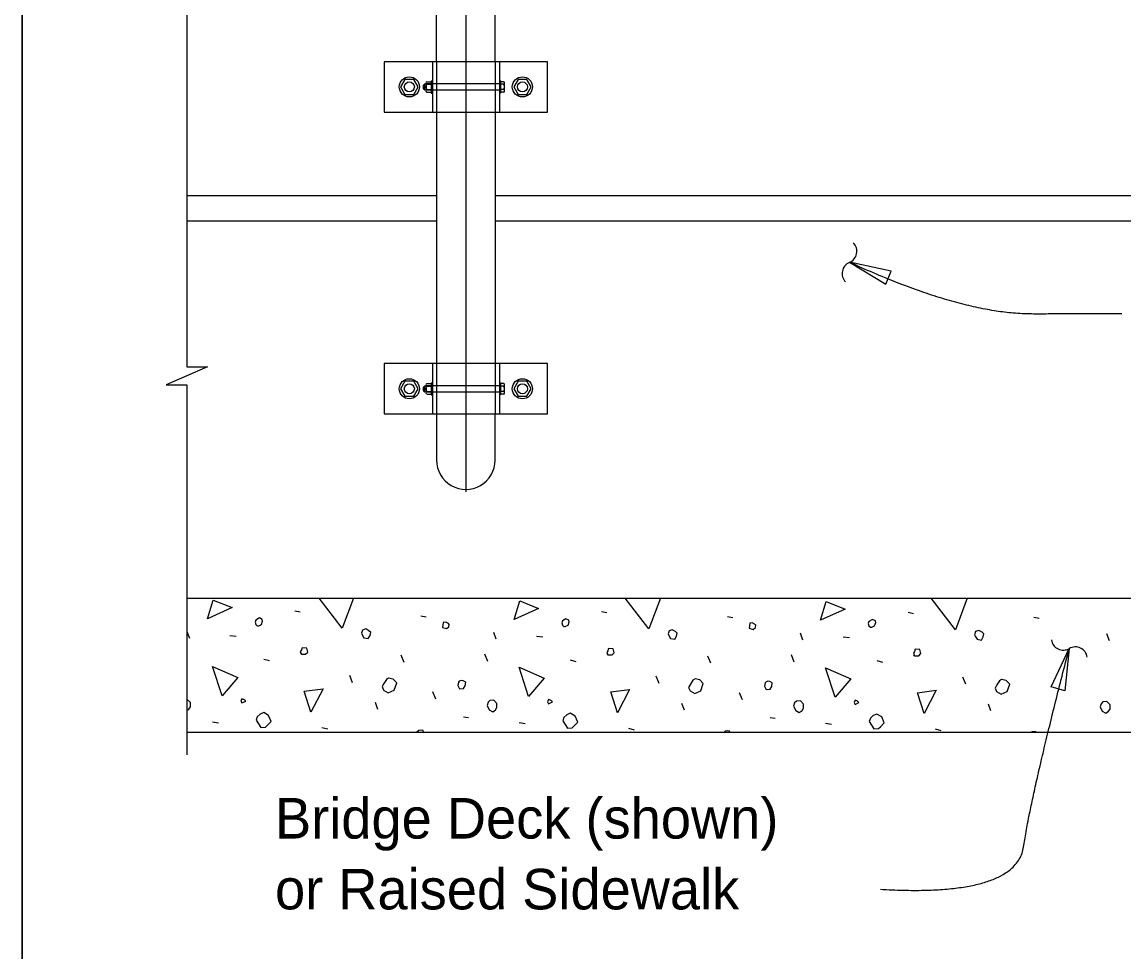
# Model space of a CAD drawing. Extents: x 0 to 41.2, y 0 to 26.
# Drawn here: x 0 to 5.48, y 12.38 to 17 of the extents above; entities that cross this region are included whole.
import ezdxf

# ---------------------------------------------------------------- set-up
doc = ezdxf.new("R2010")
doc.units = 0
for name, color, linetype in [('ActivePts-ConstElements', 7, 'Continuous'), ('CL_Major', 7, 'Continuous'), ('Dimension', 7, 'Continuous'), ('Miscellaneous', 7, 'Continuous'), ('Miscellaneous1', 7, 'Continuous'), ('SteelMisc', 7, 'Continuous'), ('SteelMisc_h', 7, 'Continuous'), ('SupstrConc', 7, 'Continuous')]:
    doc.layers.add(name, color=color, linetype=linetype)

msp = doc.modelspace()

# ---------------------------------------------------------------- linework, layer by layer
at = {"layer": 'ActivePts-ConstElements'}
msp.add_lwpolyline([(0, 0), (41.2106, 0), (41.2106, 25.96), (0, 25.96)], close=True, dxfattribs=at)
at = {"layer": 'CL_Major'}
msp.add_line((2.2062, 25.5043), (2.2062, 14.6639), dxfattribs=at)
at = {"layer": 'Dimension'}
for points in [[(0.8194, 20.1983), (0.8194, 19.1806), (0.9227, 19.1806), (0.8194, 19.1356), (0.716, 19.0906), (0.8194, 19.0906), (0.8194, 16.8862)], [(0.8194, 17.1362), (0.8194, 15.2854), (0.9227, 15.2854), (0.8194, 15.2404), (0.716, 15.1954), (0.8194, 15.1954), (0.8194, 13.3576)]]:
    msp.add_lwpolyline(points, dxfattribs=at)
for points in [[(4.1133, 15.8046), (4.2942, 15.6956), (4.32, 15.7612)], [(5.2051, 13.8856), (5.1828, 13.6755), (5.1149, 13.6946)]]:
    msp.add_lwpolyline(points, close=True, dxfattribs=at)
for centre, start, end in [((4.09, 15.8588), 292.7091, 44.4364), ((4.136, 15.7489), 112.7091, 224.4364), ((5.1759, 13.9368), 188.4294, 300.1567), ((5.2358, 13.8337), 8.4294, 120.1567)]:
    msp.add_arc(centre, 0.0596, start, end, dxfattribs=at)
for points in [[(5.467, 15.5476), (5.3703, 15.5476), (4.6709, 15.5476), (4.1132, 15.8046)], [(4.2666, 12.6889), (4.9423, 12.6495), (5.0161, 13.1567), (5.2052, 13.8855)]]:
    msp.add_open_spline(points, degree=2, dxfattribs=at)
at = {"layer": 'Miscellaneous'}
for p, q in [((1.9986, 16.6691), (1.9986, 16.6812)), ((2.0043, 16.6691), (2.0043, 16.6812)), ((1.9986, 15.1691), (1.9986, 15.1812)), ((2.0043, 15.1691), (2.0043, 15.1812)), ((1.3567, 14.0725), (1.3832, 14.0672)), ((1.9825, 14.0477), (2.009, 14.0424)), ((2.8805, 14.0689), (2.907, 14.0636)), ((3.5063, 14.0442), (3.5328, 14.0389)), ((4.4043, 14.0654), (4.4308, 14.0601)), ((5.0301, 14.0407), (5.0566, 14.0354)), ((0.8334, 13.9346), (0.821, 13.9682)), ((1.0332, 13.9505), (1.065, 13.947)), ((2.3572, 13.9311), (2.3448, 13.9646)), ((2.557, 13.947), (2.5888, 13.9434)), ((3.881, 13.9275), (3.8687, 13.9611)), ((4.0808, 13.9434), (4.1126, 13.9399)), ((5.4048, 13.924), (5.3925, 13.9576)), ((1.2011, 13.8321), (1.2294, 13.825)), ((1.8994, 13.8162), (1.8852, 13.8515)), ((2.3148, 13.8215), (2.3006, 13.8568)), ((2.7249, 13.8285), (2.7532, 13.8215)), ((3.4232, 13.8126), (3.409, 13.848)), ((3.8386, 13.8179), (3.8245, 13.8533)), ((4.2487, 13.825), (4.277, 13.8179)), ((1.643, 13.7154), (1.6289, 13.7507)), ((3.1669, 13.7119), (3.1527, 13.7472)), ((4.6907, 13.7083), (4.6765, 13.7437)), ((2.0567, 13.6341), (2.0426, 13.6694)), ((3.5805, 13.6305), (3.5664, 13.6659)), ((1.7686, 13.5828), (1.7562, 13.6164)), ((3.2924, 13.5793), (3.28, 13.6129)), ((4.8162, 13.5757), (4.8038, 13.6093)), ((2.1946, 13.5457), (2.2193, 13.5421)), ((3.7184, 13.5421), (3.7431, 13.5386)), ((0.9465, 13.5209), (0.9766, 13.5156)), ((1.491, 13.4927), (1.5193, 13.4856)), ((2.4704, 13.5174), (2.5004, 13.5121)), ((3.0148, 13.4891), (3.0431, 13.482)), ((3.9942, 13.5139), (4.0242, 13.5086)), ((4.5386, 13.4856), (4.5669, 13.4785))]:
    msp.add_line(p, q, dxfattribs=at)
for points in [[(1.5918, 13.9859), (1.4776, 14.1361)], [(1.6479, 14.1361), (1.5918, 13.9859)], [(3.1156, 13.9823), (2.9987, 14.1361)], [(3.1731, 14.1361), (3.1156, 13.9823)], [(4.6394, 13.9788), (4.5198, 14.1361)], [(4.6982, 14.1361), (4.6394, 13.9788)], [(0.9218, 14.0336), (0.9501, 14.1255), (1.0438, 14.0884), (0.9218, 14.0336)], [(2.4456, 14.0301), (2.4739, 14.122), (2.5676, 14.0849), (2.4456, 14.0301)], [(3.9694, 14.0265), (3.9977, 14.1184), (4.0914, 14.0813), (3.9694, 14.0265)], [(1.1693, 13.9982), (1.1763, 13.9982), (1.1905, 14.0053), (1.1958, 14.0212), (1.194, 14.0301), (1.1799, 14.0371), (1.1622, 14.0265), (1.1587, 14.0159), (1.1622, 14.0053), (1.1693, 13.9982)], [(2.6931, 13.9947), (2.7002, 13.9947), (2.7143, 14.0018), (2.7196, 14.0177), (2.7178, 14.0265), (2.7037, 14.0336), (2.686, 14.023), (2.6825, 14.0124), (2.686, 14.0018), (2.6931, 13.9947)], [(4.2169, 13.9912), (4.224, 13.9912), (4.2381, 13.9982), (4.2434, 14.0141), (4.2417, 14.023), (4.2275, 14.0301), (4.2098, 14.0194), (4.2063, 14.0088), (4.2098, 13.9982), (4.2169, 13.9912)], [(1.6908, 13.954), (1.6996, 13.9381), (1.7208, 13.9346), (1.7297, 13.9505), (1.7332, 13.9646), (1.7244, 13.9735), (1.7084, 13.9823), (1.6925, 13.977), (1.6872, 13.9611), (1.6908, 13.954)], [(2.0903, 13.9894), (2.1097, 13.9841), (2.1221, 13.9929), (2.1239, 14.0053), (2.1203, 14.0088), (2.1062, 14.0159), (2.0938, 14.0141), (2.0921, 14.0018), (2.0903, 13.9894)], [(3.2146, 13.9505), (3.2234, 13.9346), (3.2446, 13.9311), (3.2535, 13.947), (3.257, 13.9611), (3.2482, 13.9699), (3.2323, 13.9788), (3.2164, 13.9735), (3.211, 13.9576), (3.2146, 13.9505)], [(3.6141, 13.9859), (3.6335, 13.9806), (3.6459, 13.9894), (3.6477, 14.0018), (3.6442, 14.0053), (3.63, 14.0124), (3.6176, 14.0106), (3.6159, 13.9982), (3.6141, 13.9859)], [(4.7384, 13.947), (4.7472, 13.9311), (4.7685, 13.9275), (4.7773, 13.9434), (4.7808, 13.9576), (4.772, 13.9664), (4.7561, 13.9753), (4.7402, 13.9699), (4.7349, 13.954), (4.7384, 13.947)], [(1.3885, 13.8568), (1.4097, 13.8568), (1.4203, 13.8674), (1.415, 13.8869), (1.392, 13.8886), (1.3885, 13.878), (1.3832, 13.8692), (1.3885, 13.8568), (1.3849, 13.8603)], [(2.9123, 13.8533), (2.9335, 13.8533), (2.9441, 13.8639), (2.9388, 13.8833), (2.9158, 13.8851), (2.9123, 13.8745), (2.907, 13.8657), (2.9123, 13.8533), (2.9088, 13.8568)], [(4.4361, 13.8497), (4.4573, 13.8497), (4.4679, 13.8603), (4.4626, 13.8798), (4.4396, 13.8816), (4.4361, 13.871), (4.4308, 13.8621), (4.4361, 13.8497), (4.4326, 13.8533)], [(0.9943, 13.65), (0.9465, 13.7967), (1.0721, 13.7419), (0.9943, 13.65)], [(2.5181, 13.6464), (2.4704, 13.7932), (2.5959, 13.7384), (2.5181, 13.6464)], [(4.0419, 13.6429), (3.9942, 13.7896), (4.1197, 13.7348), (4.0419, 13.6429)], [(1.7968, 13.6783), (1.8198, 13.6659), (1.8499, 13.6783), (1.8622, 13.7154), (1.8446, 13.7331), (1.8216, 13.7384), (1.811, 13.7313), (1.7986, 13.7119), (1.7898, 13.6959), (1.7968, 13.6783)], [(2.1663, 13.7012), (2.1751, 13.6853), (2.1946, 13.6871), (2.2034, 13.6995), (2.2052, 13.7189), (2.1928, 13.7242), (2.184, 13.726), (2.1734, 13.7225), (2.1698, 13.7189), (2.1663, 13.7012)], [(3.3207, 13.6747), (3.3436, 13.6624), (3.3737, 13.6747), (3.3861, 13.7119), (3.3684, 13.7295), (3.3454, 13.7348), (3.3348, 13.7278), (3.3224, 13.7083), (3.3136, 13.6924), (3.3207, 13.6747)], [(3.6901, 13.6977), (3.699, 13.6818), (3.7184, 13.6836), (3.7272, 13.6959), (3.729, 13.7154), (3.7166, 13.7207), (3.7078, 13.7225), (3.6972, 13.7189), (3.6936, 13.7154), (3.6901, 13.6977)], [(4.8445, 13.6712), (4.8674, 13.6588), (4.8975, 13.6712), (4.9099, 13.7083), (4.8922, 13.726), (4.8692, 13.7313), (4.8586, 13.7242), (4.8462, 13.7048), (4.8374, 13.6889), (4.8445, 13.6712)], [(1.4362, 13.5687), (1.4026, 13.673), (1.4963, 13.6853), (1.4362, 13.5687)], [(2.96, 13.5651), (2.9264, 13.6694), (3.0201, 13.6818), (2.96, 13.5651)], [(4.4838, 13.5616), (4.4503, 13.6659), (4.5439, 13.6783), (4.4838, 13.5616)], [(0.8193, 13.5766), (0.8299, 13.5846), (0.8369, 13.5952), (0.8369, 13.6164), (0.821, 13.6323), (0.8193, 13.6321)], [(1.0933, 13.6146), (1.1127, 13.6235), (1.1056, 13.6305), (1.0933, 13.6358), (1.088, 13.6235), (1.0933, 13.6146)], [(2.3113, 13.6023), (2.3219, 13.581), (2.3395, 13.5704), (2.3537, 13.581), (2.3608, 13.5916), (2.3608, 13.6129), (2.3448, 13.6288), (2.3254, 13.627), (2.3166, 13.6182), (2.3113, 13.6023)], [(2.6171, 13.6111), (2.6365, 13.6199), (2.6295, 13.627), (2.6171, 13.6323), (2.6118, 13.6199), (2.6171, 13.6111)], [(3.8351, 13.5987), (3.8457, 13.5775), (3.8634, 13.5669), (3.8775, 13.5775), (3.8846, 13.5881), (3.8846, 13.6093), (3.8687, 13.6252), (3.8492, 13.6235), (3.8404, 13.6146), (3.8351, 13.5987)], [(4.1409, 13.6076), (4.1603, 13.6164), (4.1533, 13.6235), (4.1409, 13.6288), (4.1356, 13.6164), (4.1409, 13.6076)], [(5.3589, 13.5952), (5.3695, 13.574), (5.3872, 13.5634), (5.4013, 13.574), (5.4084, 13.5846), (5.4084, 13.6058), (5.3925, 13.6217), (5.373, 13.6199), (5.3642, 13.6111), (5.3589, 13.5952)], [(1.164, 13.5298), (1.187, 13.4927), (1.2099, 13.4944), (1.2188, 13.5033), (1.2382, 13.5227), (1.2258, 13.5528), (1.2011, 13.5669), (1.1834, 13.5598), (1.1693, 13.5457), (1.164, 13.5298)], [(2.6878, 13.5262), (2.7108, 13.4891), (2.7338, 13.4909), (2.7426, 13.4997), (2.762, 13.5192), (2.7497, 13.5492), (2.7249, 13.5634), (2.7072, 13.5563), (2.6931, 13.5421), (2.6878, 13.5262)], [(4.2116, 13.5227), (4.2346, 13.4856), (4.2576, 13.4873), (4.2664, 13.4962), (4.2859, 13.5156), (4.2735, 13.5457), (4.2487, 13.5598), (4.2311, 13.5528), (4.2169, 13.5386), (4.2116, 13.5227)], [(1.9949, 13.4695), (1.9931, 13.4785), (1.9842, 13.4803), (1.9718, 13.4785), (1.9628, 13.4695)], [(3.518, 13.4695), (3.5169, 13.475), (3.508, 13.4767), (3.4957, 13.475), (3.4901, 13.4695)], [(5.0411, 13.4695), (5.0407, 13.4714), (5.0318, 13.4732), (5.0195, 13.4714), (5.0175, 13.4695)]]:
    msp.add_lwpolyline(points, dxfattribs=at)
at = {"layer": 'Miscellaneous1'}
msp.add_lwpolyline([(0, 25.96), (41.2106, 25.96), (41.2106, 0), (0, 0)], close=True, dxfattribs=at)
at = {"layer": 'SteelMisc'}
for p, q in [((2.0603, 16.801), (2.0603, 17.4631)), ((2.352, 16.801), (2.352, 17.4631)), ((2.6121, 16.801), (1.8002, 16.801)), ((1.8002, 16.801), (1.8002, 16.551)), ((2.0395, 16.801), (2.0395, 16.551)), ((2.3728, 16.801), (2.3728, 16.551)), ((2.6121, 16.551), (2.6121, 16.801)), ((2.033, 16.7063), (2.033, 16.6457)), ((2.033, 16.7063), (2.0395, 16.7063)), ((2.3791, 16.7063), (2.3731, 16.7063)), ((2.3791, 16.7063), (2.3791, 16.6457)), ((1.9958, 16.684), (2.0014, 16.6906)), ((1.9958, 16.6663), (1.9958, 16.684)), ((1.9958, 16.6663), (2.0014, 16.6607)), ((2.0014, 16.6906), (2.008, 16.6906)), ((2.0014, 16.6607), (2.0014, 16.6906)), ((2.0014, 16.6607), (2.008, 16.6607)), ((2.008, 16.6939), (2.008, 16.6582)), ((2.0127, 16.689), (2.033, 16.689)), ((2.0127, 16.6631), (2.033, 16.6631)), ((2.0129, 16.702), (2.033, 16.702)), ((2.033, 16.702), (2.033, 16.65)), ((2.3938, 16.702), (2.3791, 16.702)), ((2.3939, 16.689), (2.3791, 16.689)), ((2.3939, 16.663), (2.3791, 16.663)), ((2.3989, 16.6566), (2.3989, 16.6955)), ((2.013, 16.65), (2.033, 16.65)), ((2.033, 16.6457), (2.0395, 16.6457)), ((2.3791, 16.6457), (2.3731, 16.6457)), ((2.3938, 16.65), (2.3791, 16.65)), ((1.8002, 16.551), (2.6121, 16.551)), ((2.0603, 16.551), (2.0603, 15.301)), ((2.352, 16.551), (2.352, 15.301)), ((2.6121, 15.301), (1.8002, 15.301)), ((1.8002, 15.301), (1.8002, 15.051)), ((2.0395, 15.301), (2.0395, 15.051)), ((2.3728, 15.301), (2.3728, 15.051)), ((2.6121, 15.051), (2.6121, 15.301)), ((1.9958, 15.184), (2.0014, 15.1906)), ((1.9958, 15.1663), (1.9958, 15.184)), ((2.0014, 15.1906), (2.008, 15.1906)), ((2.0014, 15.1607), (2.0014, 15.1906)), ((2.008, 15.1939), (2.008, 15.1582)), ((2.0127, 15.189), (2.033, 15.189)), ((2.0129, 15.202), (2.033, 15.202)), ((2.033, 15.2063), (2.033, 15.1457)), ((2.033, 15.2063), (2.0395, 15.2063)), ((2.033, 15.202), (2.033, 15.15)), ((2.3791, 15.2063), (2.3731, 15.2063)), ((2.3791, 15.2063), (2.3791, 15.1457)), ((2.3938, 15.202), (2.3791, 15.202)), ((2.3939, 15.189), (2.3791, 15.189)), ((2.3989, 15.1566), (2.3989, 15.1955)), ((1.9958, 15.1663), (2.0014, 15.1607)), ((2.0014, 15.1607), (2.008, 15.1607)), ((2.0127, 15.1631), (2.033, 15.1631)), ((2.013, 15.15), (2.033, 15.15)), ((2.033, 15.1457), (2.0395, 15.1457)), ((2.3791, 15.1457), (2.3731, 15.1457)), ((2.3939, 15.163), (2.3791, 15.163)), ((2.3938, 15.15), (2.3791, 15.15)), ((1.8002, 15.051), (2.6121, 15.051)), ((2.0602, 15.051), (2.0602, 14.8218)), ((2.3519, 14.8218), (2.3519, 15.051))]:
    msp.add_line(p, q, dxfattribs=at)
for points in [[(1.9468, 16.7135), (1.9035, 16.7135), (1.8818, 16.676), (1.9035, 16.6385), (1.9468, 16.6385), (1.9685, 16.676)], [(2.5088, 16.7135), (2.4655, 16.7135), (2.4438, 16.676), (2.4655, 16.6385), (2.5088, 16.6385), (2.5305, 16.676)], [(1.9468, 15.2135), (1.9035, 15.2135), (1.8818, 15.176), (1.9035, 15.1385), (1.9468, 15.1385), (1.9685, 15.176)], [(2.5088, 15.2135), (2.4655, 15.2135), (2.4438, 15.176), (2.4655, 15.1385), (2.5088, 15.1385), (2.5305, 15.176)]]:
    msp.add_lwpolyline(points, close=True, dxfattribs=at)
for centre, radius in [((1.9252, 16.676), 0.05), ((2.4871, 16.676), 0.05), ((1.9252, 16.676), 0.025), ((2.4871, 16.676), 0.025), ((1.9252, 15.176), 0.05), ((1.9252, 15.176), 0.025), ((2.4871, 15.176), 0.05), ((2.4871, 15.176), 0.025)]:
    msp.add_circle(centre, radius, dxfattribs=at)
for centre, radius, start, end in [((2.0145, 16.6955), 0.00674, 104.4891, 254.1889), ((2.0274, 16.676), 0.0196, 138.628, 221.372), ((2.0145, 16.6565), 0.00673, 105.7823, 255.5404), ((2.3921, 16.6955), 0.00673, 285.7823, 75.5404), ((2.3921, 16.6565), 0.00674, 284.4891, 74.1889), ((2.3792, 16.676), 0.0196, 318.628, 41.372), ((2.0145, 15.1955), 0.00674, 104.4891, 254.1889), ((2.0274, 15.176), 0.0196, 138.628, 221.372), ((2.3921, 15.1955), 0.00673, 285.7823, 75.5404), ((2.3792, 15.176), 0.0196, 318.628, 41.372), ((2.0145, 15.1565), 0.00673, 105.7823, 255.5404), ((2.3921, 15.1565), 0.00674, 284.4891, 74.1889)]:
    msp.add_arc(centre, radius, start, end, dxfattribs=at)
msp.add_ellipse((2.2062, 14.8218), major_axis=(0, 0.1458), ratio=0.999499, start_param=1.570796, end_param=4.712389, dxfattribs=at)
at = {"layer": 'SteelMisc_h'}
for p, q in [((2.0603, 16.801), (2.0603, 16.551)), ((2.352, 16.801), (2.352, 16.551)), ((2.3729, 16.6906), (2.008, 16.6906)), ((2.008, 16.6607), (2.3729, 16.6607)), ((2.0603, 15.301), (2.0603, 15.051)), ((2.352, 15.301), (2.352, 15.051)), ((2.3729, 15.1906), (2.008, 15.1906)), ((2.008, 15.1607), (2.3729, 15.1607))]:
    msp.add_line(p, q, dxfattribs=at)
at = {"layer": 'SupstrConc'}
for p, q in [((0.8193, 16.1361), (2.0603, 16.1361)), ((2.352, 16.1361), (12.0604, 16.1361)), ((0.8193, 16.0111), (2.0603, 16.0111)), ((2.352, 16.0111), (12.0604, 16.0111)), ((0.8193, 14.1361), (23.5931, 14.1361)), ((0.8193, 13.4695), (23.5931, 13.4695))]:
    msp.add_line(p, q, dxfattribs=at)

# ---------------------------------------------------------------- texts
at = {"layer": 'Dimension'}
for s, p in [('Bridge Deck (shown)', (1.2575, 12.9409)), ('or Raised Sidewalk', (1.2575, 12.5889))]:
    msp.add_text(s, height=0.2016, dxfattribs=at).set_placement(p)

doc.saveas('drawing.dxf')
